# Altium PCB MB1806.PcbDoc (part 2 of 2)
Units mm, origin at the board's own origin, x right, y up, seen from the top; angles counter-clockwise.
Board outline 43.1 x 47.12 mm, 4 copper layers (Top Layer, Internal 1, Internal 2, Bottom Layer), stack 1.565 mm thick; 88 components, 68 nets, 317 pads, 562 vias.
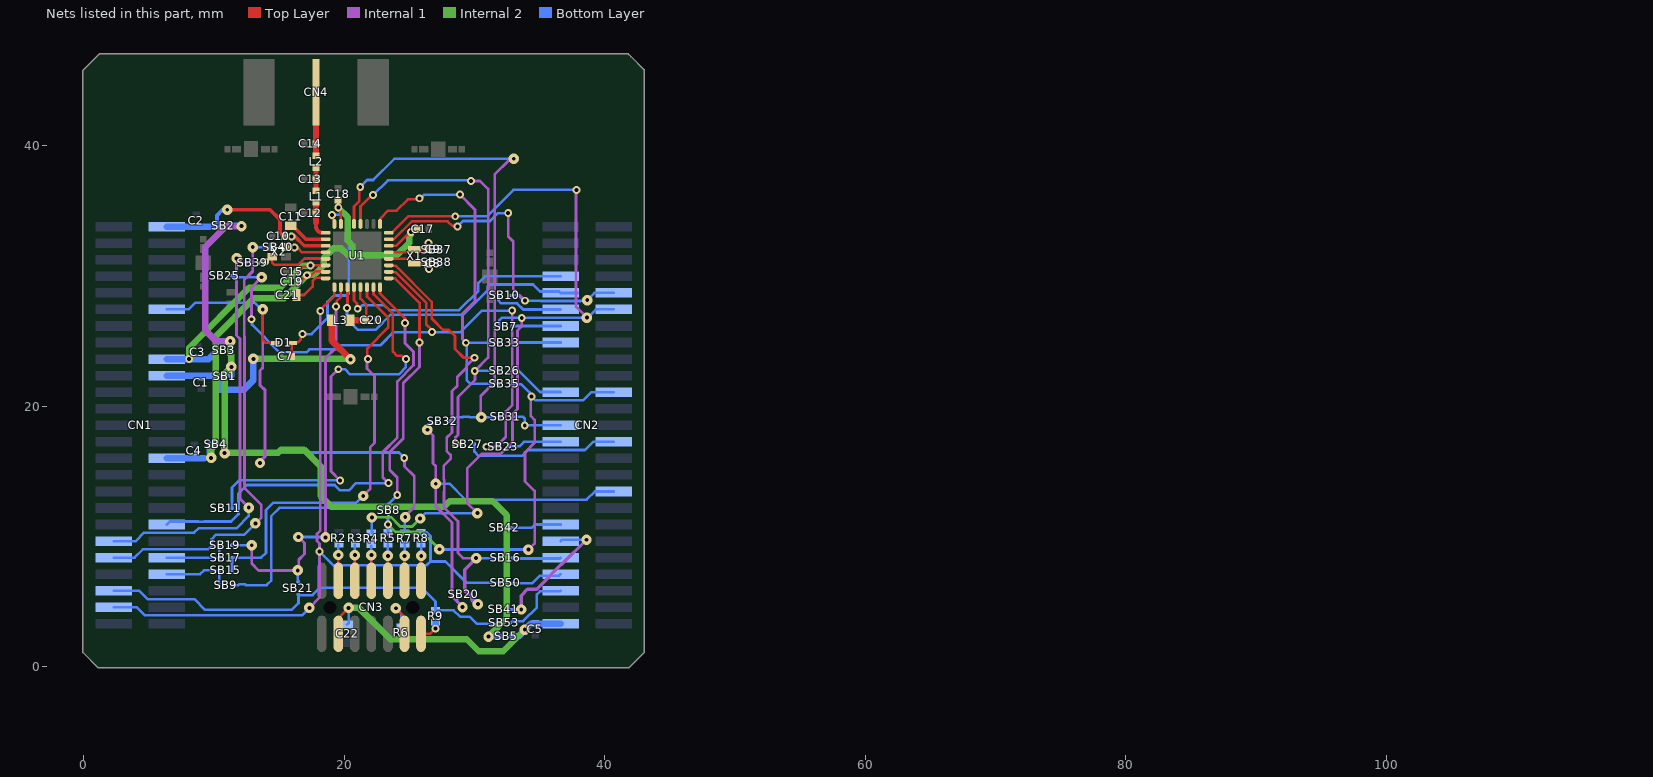
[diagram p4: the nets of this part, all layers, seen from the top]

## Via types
v1: diameter 0.6, hole 0.3, Top Layer to Bottom Layer, tented both sides, 505 vias
v2: diameter 0.8, hole 0.3, Top Layer to Bottom Layer, tented both sides, 57 vias

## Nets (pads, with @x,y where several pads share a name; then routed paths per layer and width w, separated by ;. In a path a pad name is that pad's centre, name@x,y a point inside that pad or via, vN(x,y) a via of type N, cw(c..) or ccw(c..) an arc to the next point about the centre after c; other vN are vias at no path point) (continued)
GPIO18: CN1.38 U1.8 | length 36.6
  Top Layer w0.2: U1.8@22.764,29.15 22.764,28.667 22.769,28.667 24.682,26.754 v1@24.682,26.668
  Internal 1 w0.21: v1(23.406,14.113) 22.975,14.545 22.975,16.48 24.092,17.598 24.092,21.916 25.337,23.16 25.337,24.193 24.689,24.841 v1(24.689,26.388)
  Bottom Layer w0.2: CN1.38@6.398,10.928 6.637,11.167 8.797,11.167 8.814,11.15 9.27,11.15 9.286,11.167 11.342,11.167 11.899,11.723 11.899,13.298 12.561,13.961 19.284,13.961 19.69,13.554 20.379,13.554 20.938,14.113 v1(23.406,14.113)
GPIO21: CN1.42 SB17.1 SB19.1 | length 4.9
  Bottom Layer w0.2: CN1.42@6.398,8.388 SB17.1@10.375,8.388 ; SB17.1@10.428,8.381 SB19.1@10.428,9.309
GPIO22: CN1.44 SB9.1 SB15.1 | length 5.3
  Bottom Layer w0.2: CN1.44@6.398,7.118 8.944,7.118 9.239,7.413 SB15.1@10.435,7.413 SB9.1@10.435,6.277
GPIO23: CN1.45 R9.1 SB21.1 SB53.2 | length 32.8
  Bottom Layer w0.2: CN1.45@2.334,5.848 4.274,5.848 4.925,5.198 8.522,5.198 9.337,4.382 15.987,4.382 16.506,4.901 SB21.1@16.506,5.512 ; SB21.1@16.481,5.512 SB21.1@16.506,5.512 ; SB21.1@16.506,5.603 SB21.1@16.506,5.512 ; SB53.2@31.802,3.379 31.787,3.379 31.717,3.308 30.193,3.308 29.643,3.858 28.906,3.858 28.415,4.35 R9.1@27.024,4.35 27.024,5.009 25.952,6.081 18.164,6.081 17.596,5.512 SB21.1@16.506,5.512
GPIO24: CN1.47 R8.2 SB50.1 U1.1 | length 59.1
  Top Layer w0.2: v1@18.015,27.227 19.264,28.475 U1.1@19.264,29.15
  Internal 1 w0.21: v2(17.336,4.537) 18.123,5.325 v1(18.123,8.855) 18.123,9.478 17.925,9.676 17.925,10.219 18.182,10.475 v1(18.182,27.312)
  Bottom Layer w0.2: CN1.47@2.334,4.578 4.102,4.578 4.728,3.953 16.777,3.953 17.336,4.512 v2(17.336,4.537)
  Bottom Layer w0.21: v1(18.123,8.855) 19.165,7.814 26.353,7.814 26.632,8.093 ; R8.2@25.922,10.328 26.353,10.328 26.632,10.049 26.632,8.093 ; SB50.1@31.922,6.445 31.915,6.452 29.421,6.452 27.78,8.093 26.632,8.093
GPIO28: CN2.7 U1.4 | length 19
  Top Layer w0.2: U1.4@20.764,29.15 20.764,28.134 21.001,27.897 21.001,27.542 v1(21.048,27.495)
  Bottom Layer w0.2: v1(21.048,27.495) 21.138,27.495 21.393,27.751 23.103,27.751 23.473,27.381 28.842,27.381 30.31,28.849 30.31,29.468 30.82,29.978 CN2.7@36.624,29.978
GPIO29: CN2.9 U1.3 | length 22.4
  Top Layer w0.2: v1(20.231,27.542) 20.264,27.574 U1.3@20.264,29.15
  Bottom Layer w0.2: v1(20.231,27.542) 20.231,26.723 21.076,25.879 22.416,25.879 23.568,27.031 29.165,27.031 31.026,28.893 31.026,29.236 31.144,29.353 34.509,29.353 35.045,28.818 36.515,28.818 CN2.9@36.624,28.708
  Bottom Layer w0.21: CN2.9@36.624,28.708 CN2.9@37.926,28.708
GPIO30: CN2.10 SB10.1 U1.15 | length 25.9
  Top Layer w0.2: U1.15@23.439,32.825 23.458,32.844 23.837,32.844 25.199,34.206 27.96,34.206 28.317,33.848 28.665,33.848 v1(28.715,33.798)
  Internal 1 w0.21: v1(32.601,34.835) 32.601,33.055 32.982,32.674 32.982,29.014 v1(33.886,28.11)
  Bottom Layer w0.2: v1(28.715,33.798) 29.143,34.225 31.21,34.225 31.82,34.835 v1(32.601,34.835) ; SB10.1@32.826,28.514 33.388,28.514 33.791,28.11 35.103,28.11 35.124,28.09 38.125,28.09 38.138,28.103 38.616,28.103 39.221,28.708 CN2.10@40.688,28.708
  other v2: 38.672,28.159
GPIO31: CN2.11 SB10.2 | length 5.4
  Bottom Layer w0.21: SB10.2@31.851,28.423 31.851,28.117 32.059,27.909 33.289,27.909 33.76,27.438 CN2.11@36.624,27.438
GPIO32: CN2.12 R4.2 SB7.1 U1.16 | length 63.4
  Top Layer w0.2: U1.16@23.439,33.325 23.471,33.358 23.696,33.358 24.924,34.585 v1(28.537,34.585)
  Internal 1 w0.21: v2(30.239,11.802) 29.452,12.589 29.452,15.227 30.563,16.338 32.007,16.338 32.931,17.263 32.931,19.422 33.312,19.803 33.312,25.822 33.643,26.153 v1(33.643,26.788) ; v1(37.849,36.618) 37.808,36.578 37.808,27.651 v2(38.646,26.813)
  Internal 2 w0.21: v2(22.136,11.471) 22.195,11.471 22.216,11.493 23.611,11.493 24.318,10.786 25.235,10.786 v2(25.845,11.395)
  Bottom Layer w0.2: R4.2@22.118,10.302 22.187,10.372 22.136,10.423 v2(22.136,11.471) ; v2(25.845,11.395) 26.251,11.802 v2(30.239,11.802) ; v1(28.537,34.585) 30.976,34.585 33.008,36.617 v1(37.849,36.618) v1(37.849,36.618) ; SB7.1@31.922,26.2 31.922,26.617 32.093,26.788 v1(33.643,26.788) 38.672,26.788 39.323,27.438 CN2.12@40.688,27.438
GPIO33: CN2.13 SB7.2 | length 3.7
  Bottom Layer w0.2: SB7.2@32.897,26.2 32.929,26.168 CN2.13@36.624,26.168
GPIO34: CN2.15 SB33.1 | length 3.8
  Bottom Layer w0.2: SB33.1@32.844,24.832 32.91,24.898 CN2.15@36.624,24.898
GPIO37: CN2.21 SB26.1 | length 4.5
  Bottom Layer w0.2: SB26.1@32.833,22.731 33.419,22.731 35.045,21.105 36.607,21.105 CN2.21@36.624,21.088
GPIO38: CN2.22 R5.2 SB8.1 SB35.1 | length 34.1
  Internal 1 w0.21: v2(34.151,9.008) 34.176,9.008 34.633,9.465 34.633,13.505 33.897,14.242 33.897,16.47 34.633,17.207 34.633,18.964 34.343,19.255 34.343,20.715 v1(34.389,20.762)
  Internal 2 w0.21: v1(23.381,10.938) 23.965,10.354 25.997,10.354 v2(27.318,9.033)
  Bottom Layer w0.2: R5.2@23.376,10.328 23.376,11.402 ; v2(27.318,9.033) v2@27.343,9.008 ; SB35.1@32.829,21.708 32.834,21.712 32.866,21.712 32.871,21.708 33.599,21.708 34.243,21.064 34.243,21.017 34.389,20.87 v1(34.389,20.762) 34.399,20.762 34.706,20.454 38.351,20.454 38.985,21.088 CN2.22@40.688,21.088
  Bottom Layer w0.21: v2@27.343,9.008 v2(34.151,9.008)
GPIO41: CN2.25 SB31.2 | length 4.3
  Bottom Layer w0.2: SB31.2@32.911,19.193 33.745,19.193 33.871,19.066 33.871,18.548 CN2.25@36.624,18.548
  other v1: 33.871,18.533
GPIO42: CN2.27 SB23.2 | length 3.9
  Bottom Layer w0.2: 32.913,16.932 33.465,16.932 33.811,17.278 CN2.27@36.624,17.278
GPIO43: CN2.28 SB27.1 | length 11.9
  Bottom Layer w0.2: SB27.1@29.999,17.107 29.999,16.526 30.329,16.196 33.668,16.196 34.125,16.653 38.494,16.653 39.119,17.278 CN2.28@40.688,17.278
GPIO46: CN2.34 SB20.2 SB32.2 | length 31.3
  Internal 1 w0.21: v2(26.404,18.202) 26.835,17.771 26.835,15.612 27.039,15.408 v2(27.039,14.062) 27.039,12.334 28.283,11.089 28.283,5.401 v2(29.096,4.588)
  Internal 2 w0.21: v2(29.096,4.588) v2@29.147,4.588
  Bottom Layer w0.2: v2@26.412,18.21 v2(26.404,18.202) 26.404,18.456 26.632,18.685 26.894,18.685 ; v2@27.039,14.163 v2(27.039,14.062) 28.086,14.062 29.305,12.843 38.621,12.843 39.246,13.468 CN2.34@40.688,13.468 ; SB20.2@28.7,5.579 28.7,5.005 29.096,4.609 v2(29.096,4.588)
GPIO49: CN2.37 SB42.1 | length 3.9
  Bottom Layer w0.2: SB42.1@32.813,10.674 34.389,10.674 34.643,10.928 CN2.37@36.624,10.928
GPIO50: CN2.39 SB41.1 | length 10.7
  Internal 1 w0.254: v2(33.602,4.41) 33.602,5.472 34.082,5.952 34.781,5.952 35.911,7.082 35.911,7.096 36.679,7.864 36.713,7.864 v2(38.612,9.764)
  Bottom Layer w0.2: SB41.1@32.753,4.41 v2(33.602,4.41) ; CN2.39@36.624,9.658 36.73,9.764 v2(38.612,9.764)
GPIO52: CN2.41 SB16.2 | length 3.8
  Bottom Layer w0.2: SB16.2@32.91,8.371 32.925,8.371 32.975,8.321 36.557,8.321 CN2.41@36.624,8.388
GPIO54: CN2.45 SB53.1 | length 5.5
  Bottom Layer w0.2: SB53.1@32.777,3.379 32.789,3.379 32.921,3.511 33.744,3.511 34.807,4.574 34.807,5.57 35.045,5.807 36.583,5.807 CN2.45@36.624,5.848
GPIO55: CN2.43 SB50.2 | length 4
  Bottom Layer w0.2: SB50.2@32.897,6.445 32.912,6.445 32.948,6.408 34.444,6.408 35.045,7.009 36.515,7.009 CN2.43@36.624,7.118
NetC7_2: C7.2 D1.1 U1.24 | length 15.6
  Top Layer w0.2: D1.1@16.059,24.869 16.109,24.919 16.477,24.919 16.669,25.111 v1@16.669,25.299 ; v1(19.078,34.697) 19.154,34.62 19.154,34.362 19.264,34.252 U1.24@19.264,34 U1.24@19.245,34.019
  Top Layer w0.21: C7.2@15.997,23.83 15.997,24.807 D1.1@16.059,24.869
  Bottom Layer w0.21: v1(16.805,25.543) 17.514,25.543 18.737,26.767 18.737,28.026 19.225,28.514 20.237,28.514 20.36,28.637 20.36,34.574 20.237,34.697 v1(19.078,34.697)
NetC8_2: C8.2 SB38.1 U1.12 X1.2 | length 3.2
  Top Layer w0.2: U1.12@23.439,31.325 24.826,31.325 25.021,31.13 25.021,31.08 25.078,31.022 26.153,31.022 C8.2@26.212,30.964 ; X1.2@25.093,30.93 X1.2@25.343,30.93
  other v1: 26.521,30.542
NetC9_2: C9.2 SB37.1 U1.13 X1.1 | length 3
  Top Layer w0.2: U1.13@23.439,31.825 24.888,31.825 25.093,32.03 X1.1@25.343,32.03 ; X1.1@25.306,32.068 X1.1@25.343,32.032 ; X1.1@25.421,32.03 26.291,32.03 26.369,32.108 C9.2@26.374,32.113
  other v1: 26.49,32.531
NetC11_2: C11.2 U1.26 | length 3
  Top Layer w0.3: C11.2@16.057,33.866 17.097,32.825 U1.26@18.589,32.825
NetC12_2: C12.2 L1.1 U1.25 | length 2.5
  Top Layer w0.3: 17.856,33.811 ccw(c18.342,33.811) 18.342,33.325 U1.25@18.589,33.325
  Top Layer w0.4: C12.2@17.823,34.852 C12.2@17.856,34.885
  Top Layer w0.45: 17.859,34.116 17.859,34.844 L1.1@17.859,35.54
NetC13_2: C13.2 L1.2 L2.1 | length 1.8
  Top Layer w0.4: L1.2@17.805,36.569 L1.2@17.819,36.556 ; L1.2@17.854,36.556 C13.2@17.854,37.43 L2.1@17.854,38.335
NetC14_2: C14.2 CN4.1 L2.2 | length 4.7
  Top Layer w0.45: L2.2@17.854,39.236 C14.2@17.854,40.142 CN4.1@17.854,43.891
NetC20_2: C20.2 L3.2 U1.5 | length 3.8
  Top Layer w0.2: L3.2@20.635,26.617 L3.2@20.642,26.624 ; U1.5@21.264,29.15 21.251,29.138 21.251,28.276 21.697,27.831 21.697,26.624 C20.2@21.729,26.624
  Top Layer w0.5: L3.2@20.642,26.624 C20.2@21.697,26.624
NetC21_2: C21.2 U1.32 | length 3
  Top Layer w0.2: C21.2@16.349,28.545 16.937,28.545 17.595,29.203 17.595,29.636 17.817,29.858 U1.32@18.52,29.858
NetCN3_4: CN3.4 R2.1 | length 2.8
  Top Layer w0.2: CN3.4@19.561,6.614 v2(19.561,8.589) v2@19.561,8.639
  Bottom Layer w0.2: v2(19.561,8.589) R2.1@19.561,9.384
NetCN3_6: CN3.6 R3.1 | length 2.8
  Top Layer w0.2: CN3.6@20.831,6.614 v2(20.831,8.579)
  Bottom Layer w0.2: v2(20.831,8.579) R3.1@20.831,9.372
NetCN3_8: CN3.8 R4.1 | length 2.7
  Top Layer w0.2: CN3.8@22.101,6.614 v2(22.101,8.579)
  Bottom Layer w0.2: v2(22.101,8.579) R4.1@22.101,9.31
NetCN3_10: CN3.10 R5.1 | length 2.8
  Top Layer w0.2: CN3.10@23.371,6.614 v2(23.371,8.519)
  Bottom Layer w0.2: v2(23.371,8.519) R5.1@23.371,9.423
NetCN3_11: CN3.11 R6.2 | length 3.9
  Top Layer w0.2: v2(23.976,4.504) 23.951,4.504 24.641,3.814 CN3.11@24.641,2.544
  Bottom Layer w0.2: v2(23.976,4.504) 24.386,4.094 R6.2@24.386,3.081
NetCN3_12: CN3.12 R7.1 | length 2.8
  Top Layer w0.2: CN3.12@24.641,6.614 24.641,8.519 v2(24.651,8.529)
  Bottom Layer w0.2: v2(24.651,8.529) R7.1@24.651,9.396
NetCN3_13: CN3.13 R9.2 | length 1.6
  Top Layer w0.2: CN3.13@25.911,2.544 26.591,2.544 v1@26.901,2.854
  Bottom Layer w0.5: v1@27.024,2.947 R9.2@27.024,3.45
  other v1: 27.013,2.937
NetCN3_14: CN3.14 R8.1 | length 2.8
  Top Layer w0.2: CN3.14@25.911,6.614 25.911,8.539 25.921,8.529 v2(25.926,8.529)
  Bottom Layer w0.2: v2(25.926,8.529) R8.1@25.926,9.424
NetSB1_1: SB1.1 SB2.1 SB3.1 SB4.1 SB5.1 | length 60.4
  Internal 1 w0.5: v2(11.265,25.01) 10.173,25.01 9.36,25.822 9.36,32.249 10.941,33.829 v2(12.129,33.829)
  Internal 2 w0.5: v2(11.265,25.01) 11.265,23.994 11.355,23.904 v2(11.355,23.028) 10.833,22.507 v2(10.833,16.41) 10.873,16.45 14.948,16.45 15.187,16.688 16.92,16.688 18.199,15.408 18.199,13.122 19.012,12.31 27.699,12.31 28.105,12.716 31.433,12.716 32.489,11.66 32.489,3.73 v2(31.087,2.327)
  Bottom Layer w0.5: SB4.1@10.651,17.107 10.84,16.918 10.84,16.41 v2(10.833,16.41) ; SB2.1@11.214,33.846 12.101,33.846 12.123,33.823 v2(12.129,33.829) ; v2(11.265,25.01) 11.269,25.006 SB3.1@11.269,24.295 ; SB1.1@11.355,22.342 v2(11.355,23.028) ; v2(31.087,2.327) 31.103,2.343 SB5.1@31.947,2.343
NetSB8_2: SB8.2 SB9.2 U1.9 | length 37.6
  Top Layer w0.2: U1.9@23.439,29.825 23.932,29.825 25.812,27.945 25.812,27.44 25.794,27.423
  Top Layer w0.21: v1(25.794,24.908) 25.794,27.423
  Internal 1 w0.21: v1(24.085,13.205) 24.085,14.552 23.508,15.129 23.508,16.504 24.549,17.546 24.549,21.781 25.794,23.026 v1(25.794,24.908)
  Bottom Layer w0.2: SB9.2@11.4,6.277 11.897,6.277 11.952,6.332 12.407,6.332 12.462,6.277 14.067,6.277 14.415,6.625 14.415,11.573 15.05,12.208 23.12,12.208 SB8.2@23.421,12.509 24.118,13.205 v1(24.085,13.205)
NetSB11_2: SB11.2 U1.7 | length 32.3
  Top Layer w0.2: U1.7@22.264,29.15 22.264,28.619 22.772,28.111 22.772,28.109 23.742,27.139 23.745,27.139 23.745,24.595 23.751,24.589 23.751,24.561 23.753,24.559 23.753,24.2 24.075,23.878 24.462,23.878 24.702,23.638 v1(24.753,23.638)
  Internal 1 w0.21: v1(19.561,22.851) 19.001,22.29 19.001,15.022 v1(19.705,14.317)
  Bottom Layer w0.2: SB11.2@11.399,12.177 11.399,13.764 11.976,14.342 19.681,14.342 v1(19.705,14.317) ; v1@19.52,22.851 v1(19.561,22.851) 20.076,22.851 20.473,22.454 24.203,22.454 24.753,23.003 v1(24.753,23.638)
NetSB15_2: SB15.2 SB17.2 U1.6 | length 32.7
  Top Layer w0.2: U1.6@21.764,29.15 21.764,28.42 23.381,26.803 23.381,26.051 21.789,24.459 v1@21.789,23.741
  Internal 1 w0.21: v2(21.476,13.122) 22.009,13.656 22.009,16.856 22.34,17.186 22.34,22.317 21.764,22.893 v1@21.764,23.556
  Bottom Layer w0.2: SB15.2@11.403,7.42 SB17.2@11.403,8.381 13.635,8.381 14.008,8.754 14.008,12.03 14.567,12.589 20.938,12.589 v2@21.474,13.125
  other v1: 21.84,23.635
NetSB16_1: SB16.1 SB20.1 U1.11 | length 36.3
  Top Layer w0.2: U1.11@23.439,30.825 23.458,30.806 23.952,30.806 26.734,28.024 26.734,27.189
  Top Layer w0.21: 26.734,27.189 26.734,26.737 27.595,25.875 28.038,25.875 28.516,25.397 28.516,24.409 29.192,23.734 v1(30.024,23.734)
  Internal 1 w0.21: v1(30.024,23.734) 29.41,23.12 29.41,22.962 28.69,22.241 28.69,21.573 28.291,21.174 28.291,18.007 27.877,17.593 27.877,16.584 28.183,16.278 28.183,15.971 27.66,15.448 27.66,14.367 27.694,14.333 27.694,13.454 27.682,13.442 27.682,12.234 28.741,11.175 28.741,8.743 29.136,8.347 v2(30.137,8.347)
  Internal 1 w0.254: v2(30.137,8.347) 29.267,7.477 29.267,5.835 v2(30.277,4.825)
  Bottom Layer w0.2: SB20.1@29.675,5.579 29.675,5.564 29.794,5.445 29.794,5.081 29.936,4.94 30.162,4.94 v2(30.277,4.825) ; v2(30.137,8.347) 31.873,8.347 31.887,8.361 31.925,8.361 SB16.1@31.935,8.371
NetSB19_2: SB19.2 SB21.2 U1.2 | length 32.4
  Top Layer w0.2: v1(19.381,27.671) 19.431,27.721 19.431,28.069 19.764,28.402 U1.2@19.764,29.15
  Internal 1 w0.21: v2(12.916,9.338) 12.916,7.941 13.45,7.407 v2(16.452,7.407) 16.523,7.407 16.523,8.225 16.959,8.661 16.959,9.511 v2(16.498,9.973) ; v2(18.58,9.947) 18.58,23.714 19.327,24.461
  Internal 1 w0.254: 19.327,24.461 19.381,24.515 v1(19.381,27.671)
  Bottom Layer w0.2: SB19.2@11.375,9.337 11.402,9.363 11.427,9.338 v2(12.916,9.338) ; v2(16.452,7.407) 16.452,6.632 SB21.2@16.506,6.578
  Bottom Layer w0.21: v2(16.498,9.973) 18.555,9.973 v2(18.58,9.947)
NetSB23_1: SB23.1 SB25.1 U1.10 | length 47.6
  Top Layer w0.2: U1.10@23.439,30.325 23.458,30.306 23.957,30.306 26.302,27.961 26.302,27.651
  Top Layer w0.21: 26.302,27.651 26.302,26.305 26.785,25.822 26.785,25.695 v1(26.759,25.695)
  Internal 1 w0.21: v1(12.893,26.686) 12.893,29.126 v2(13.678,29.912) ; v1(30.94,16.9) 30.947,16.893 31.648,16.893 32.423,17.669 32.423,19.599 32.906,20.082 v1(32.906,27.346)
  Bottom Layer w0.2: v1(30.94,16.9) 30.941,16.901 31.955,16.901
  Bottom Layer w0.21: SB25.1@11.352,30.022 11.462,29.912 v2(13.678,29.912) ; v1(12.893,26.686) 12.93,26.648 12.93,26.273 15.058,24.146 17.108,24.146 17.337,24.375 19.486,24.375 19.805,24.693 22.81,24.693 23.813,25.695 v1(26.759,25.695) 28.941,25.695 30.592,27.346 v1(32.906,27.346)
NetSB26_2: SB26.2 SB27.2 U1.20 | length 34.9
  Top Layer w0.2: U1.20@21.264,34 21.264,35.348 21.414,35.498 22.131,36.215 v1(22.235,36.215)
  Internal 1 w0.21: v1(28.585,17.11) 28.539,17.155 28.539,17.602 28.749,17.812 28.749,20.706 30.061,22.018 v1@30.061,22.495 ; v1(29.75,37.301) 29.753,37.303 30.442,37.303 31.066,36.68 31.066,23.753 v1(30.036,22.724)
  Bottom Layer w0.2: v1(22.235,36.215) 23.374,37.354 29.697,37.354 v1(29.75,37.301) ; v1(28.585,17.11) 28.586,17.109 29.023,17.109 SB27.2@29.024,17.107 ; v1@30.087,22.731 SB26.2@31.858,22.731
NetSB31_1: SB31.1 SB32.1 U1.21 | length 41.4
  Top Layer w0.2: U1.21@20.764,34 20.764,35.343 21.18,35.759 21.18,36.779 v1(21.247,36.846)
  Internal 1 w0.21: v2(30.544,19.168) 30.544,18.939 30.493,18.888 30.493,19.168 30.493,20.793 31.56,21.86 31.56,37.786 32.666,38.892 32.912,38.892 v2(33.025,39.005)
  Bottom Layer w0.2: v1(21.247,36.846) 21.772,37.371 22.229,37.371 23.864,39.005 v2(33.025,39.005) ; SB32.1@28.069,18.845 28.392,19.168 29.107,19.168 29.149,19.21 29.605,19.21 29.647,19.168 v2(30.544,19.168) SB31.1@31.939,19.168
NetSB33_2: SB33.2 SB35.2 U1.17 | length 27.6
  Top Layer w0.2: U1.17@22.764,34 22.783,34.019 22.783,34.41 23.394,35.021 24.029,35.021 24.898,35.89 25.729,35.89 v1(25.805,35.966)
  Internal 1 w0.21: v1(28.893,36.262) 30.061,35.093 30.061,28.083 30.015,28.037 ; v1(29.35,24.883) 29.096,25.137 29.096,27.117 30.015,28.035
  Bottom Layer w0.2: v1(25.805,35.966) 25.853,35.966 26.123,36.236 v1@28.918,36.236 ; SB35.2@31.842,21.723 29.699,21.723 29.41,22.012 29.41,24.833 29.35,24.893 SB33.2@31.852,24.893
NetSB39_1: SB39.1 U1.29 X2.1 | length 4.8
  Top Layer w0.2: X2.1@14.501,31.48 14.501,31.02 14.642,30.878 16.497,30.878 16.966,31.347 17.206,31.347 17.21,31.351 17.665,31.351 17.669,31.347 18.271,31.347 18.274,31.344 18.57,31.344 U1.29@18.589,31.325
  other v1: 13.958,31.099
NetSB40_1: SB40.1 U1.28 X2.3 | length 3.3
  Top Layer w0.2: v1(16.193,32.198) 16.269,32.121 16.498,32.121 16.794,31.825 U1.28@18.589,31.825
  Bottom Layer w0.2: SB40.1@15.424,32.198 v1(16.193,32.198)
NRST: CN1.12 D1.2 R7.2 | length 42.2
  Top Layer w0.2: v2(13.764,27.438) 13.764,25.088 13.983,24.869 D1.2@14.709,24.869
  Internal 1 w0.21: v2@13.438,15.763 v2(13.551,15.65) ; 13.551,21.617 13.551,22.749 13.764,22.962 v2(13.764,27.438) ; v1(24.626,16.043) 24.626,15.769 24.651,15.743 24.651,15.383 25.392,14.642 25.392,12.263 24.702,11.573 v2(24.702,11.493)
  Internal 1 w0.254: v2(13.551,15.65) 13.551,15.769 13.937,16.154 13.937,21.232 13.551,21.617
  Bottom Layer w0.2: CN1.12@6.398,27.438 8.061,27.438 8.587,27.964 13.137,27.964 13.932,27.169 13.983,27.219 v2(13.764,27.438) ; R7.2@24.658,10.303 v2@24.658,11.479
  Bottom Layer w0.21: v2(13.551,15.65) 13.551,15.783 14.218,16.45 24.219,16.45 v1(24.626,16.043)
OSC_IN: CN1.39 SB39.2 | length 32.2
  Internal 1 w0.21: v2(11.753,31.36) 11.753,25.448 12.01,25.191 12.01,12.911 v2(12.688,12.233)
  Bottom Layer w0.2: CN1.39@2.334,9.658 4.017,9.658 4.661,10.302 8.496,10.302 8.852,10.659 11.773,10.659 12.688,11.573 v2(12.688,12.233) ; v2(11.753,31.36) 11.773,31.379 12.123,31.029 SB39.2@12.518,31.029
OSC_OUT: CN1.41 SB40.2 | length 35.9
  Internal 1 w0.21: v2(12.992,32.223) 12.992,30.369 12.338,29.714 12.338,25.372 12.37,25.34 12.37,13.719 13.653,12.437 13.653,11.471 v2(13.196,11.014)
  Bottom Layer w0.2: CN1.41@2.334,8.388 3.915,8.388 4.56,9.033 9.557,9.033 9.825,9.301 9.825,9.79 10.186,10.151 12.357,10.151 13.221,11.014 v2(13.196,11.014) ; v2@13.069,32.198 SB40.2@14.449,32.198
VDD1: C2.2 C10.1 CN1.2 SB2.2 U1.27 | length 14.9
  Top Layer w0.3: v2@11.011,35.093 v2(11.037,35.093) 14.313,35.093 15.077,34.33 15.077,33.369 C10.1@15.401,33.045 15.419,33.026 v1(15.971,33.026) 16.244,33.026 16.945,32.325 U1.27@18.589,32.325
  Bottom Layer w0.3: SB2.2@10.239,33.846 10.239,34.651 10.681,35.093 v2(11.037,35.093)
  Bottom Layer w0.5: CN1.2@6.398,33.788 10.181,33.788 SB2.2@10.239,33.846
VDD3: C3.2 C15.1 CN1.18 SB3.2 U1.30 | length 19.3
  Top Layer w0.2: C15.1@16.446,30.342 16.446,30.367 16.601,30.522 16.651,30.522 16.853,30.724 17.361,30.724 17.462,30.825 U1.30@18.589,30.825
  Internal 2 w0.5: v1(8.116,23.638) 8.116,24.502 12.713,29.099 15.101,29.099 16.802,30.801 v1(17.437,30.801)
  Bottom Layer w0.5: CN1.18@6.398,23.628 9.627,23.628 SB3.2@10.294,24.295
VDD4: C4.2 C17.1 C18.1 C19.1 CN1.30 SB4.2 U1.14 U1.23 U1.31 | length 42.7
  Top Layer w0.2: C19.1@16.453,29.556 16.625,29.556 v1@17.107,30.039 ; 17.463,30.039 17.782,30.358 U1.31@18.52,30.358 ; v1@19.546,35.287 C18.1@19.546,35.837 ; v1(19.561,35.271) 19.561,35.163 19.764,34.961 U1.23@19.764,34 ; U1.14@23.439,32.325 24.009,32.326 25.06,33.376 v1(25.147,33.376)
  Internal 2 w0.5: v2(9.795,16.046) 9.795,16.735 10.173,17.113 10.173,25.391 13.094,28.312 15.405,28.312 v1(17.158,30.064) 17.177,30.083 17.71,30.083 18.45,30.823 18.45,31.383 19.19,32.123 19.77,32.123 20.28,31.614 20.638,31.614 ; v1(19.561,35.271) 19.561,35.244 20.28,34.525 20.28,32.728 20.638,32.37 20.638,31.614 ; v1(25.147,33.376) 25.128,33.357 25.128,33.19 25.022,33.084 25.022,32.565 24.07,31.614 20.638,31.614
  Bottom Layer w0.5: CN1.30@6.398,16.008 9.274,16.008 ; v2@9.676,16.41 SB4.2@9.676,17.107
VDD15: C5.2 C22.2 CN2.49 CN3.3 SB5.2 | length 23.4
  Top Layer w0.2: CN3.3@19.561,2.544 19.561,3.764 20.326,4.529 v2(20.351,4.529)
  Internal 2 w0.5: v2(20.351,4.529) 21.154,4.529 23.559,2.124 29.426,2.124 30.341,1.21 32.22,1.21 v2(33.871,2.861)
  Bottom Layer w0.2: C22.2@20.231,3.254 20.351,3.375 v2(20.351,4.529)
  Bottom Layer w0.5: SB5.2@32.922,2.343 33.404,2.343 33.871,2.81 v2(33.871,2.861) 34.319,3.308 34.474,3.308 34.492,3.326 C5.2@34.678,3.326 ; C5.2@34.678,3.308 CN2.49@36.624,3.308
VDDA: C1.2 CN1.20 L3.1 SB1.2 | length 20.7
  Top Layer w0.5: L3.1@19.049,26.612 19.049,25.056 v2(20.496,23.609)
  Internal 2 w0.5: v2(13.043,23.638) 20.46,23.638 20.485,23.663 v2@20.46,23.663
  Bottom Layer w0.5: CN1.20@6.398,22.358 10.339,22.358 SB1.2@10.368,22.329 10.368,21.259 12.28,21.259 13.043,22.022 v2(13.043,23.638)
pads on no net: CN1.3 CN1.4 CN1.5 CN1.10 CN1.11 CN1.16 CN1.19 CN1.21 CN1.23 CN1.24 CN1.26 CN1.27 CN1.29 CN1.32 CN1.43 CN1.48 CN1.50 CN2.1 CN2.3 CN2.4 CN2.5 CN2.6 CN2.16 CN2.17 CN2.18 CN2.19 CN2.23 CN2.24 CN2.29 CN2.30 CN2.31 CN2.33 CN2.35 CN2.36 CN2.40 CN2.42 CN2.46 CN2.47 CN2.48 CN3.1 CN3.2 CN3.9 CN3.NPTH1 CN3.NPTH2 Designator15.1

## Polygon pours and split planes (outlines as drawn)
GND on Top Layer "Top Layer-GND" (solid, remove dead copper, pour order 9): -6.693,52.045 44.006,52.045 44.006,-1.076 -6.693,-1.076
NetC12_2 on Top Layer "RF_OUT" (solid, pour order 5): 18.086,34.103 18.004,33.83 17.707,33.82 17.641,34.077
GND on Bottom Layer "Bottom Layer-GND" (solid, remove dead copper, pour order 7): -3.848,46.634 43.676,46.634 43.676,-1.508 -3.848,-1.508
GND on Internal 2 "Internal 2-GND" (solid, remove dead copper, pour order 11): -4.508,46.634 47.486,46.634 47.486,-0.721 -4.508,-0.721
GND on Internal 1 "Internal 1-GND" (solid, remove dead copper, pour order 13): -2.679,46.844 15.659,46.844 15.659,31.944 19.876,31.944 19.876,46.844 44.793,46.844 44.793,-1.635 -2.679,-1.635

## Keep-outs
Top Layer:
  rectangle: 17.641,36.045 18.086,36.158
Keep-Out Layer:
  lines w0.1: 43,1.141 43,45.795 41.78,47.015 1.26,47.015 0,45.755 0,1.139 1.139,0 41.852,0 42.504,0.647 43.001,1.141

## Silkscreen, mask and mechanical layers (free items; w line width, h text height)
Top Overlay:
  lines w0.05: -0.592,0 1.139,0 ; 0,-0.5 0,1.139
  lines w0.1: 18.204,35.128 18.795,37.008 ; 9.182,20.742 31.182,20.742 31.182,39.742 9.182,39.742 9.182,20.742
  text "L" at 1.245,41.838 h7.62
  text "MB1806A" at 2.769,1.988 h2.5
Bottom Overlay:
  text "H" at 40.962,42.376 h7.62
  text "C" at 35.288,41.106 h7.62
  text "I" at 40.505,38.176 h7.62
Top Solder:
  lines w1: 9.182,28.058 9.182,20.742 17.615,20.742 ; 9.182,33.925 9.182,39.742 9.944,39.742 ; 19.816,39.732 24.219,39.767 ; 23.371,20.742 31.153,20.742 31.153,26.813 ; 30.137,39.792 31.153,39.792 31.153,33.026
M1-Board Shape:
  lines w0.1: 43,1.141 43,45.795 ; 43.001,1.141 41.852,0 1.139,0 0,1.139 0,45.75 0,45.755 1.245,47 41.326,47.015 41.78,47.015 41.987,46.809 43,45.795 ; 43.001,45.795 43,45.795
M2-Board Dimensions:
  lines w0.1: -5.613,47 0.61,47 ; -5.334,0 0.889,0 ; 0,-11.198 0,0.464 ; 43,-10.994 43,0.667
  lines w0.254: -5.798,2 -5.131,0 ; -5.797,45 -5.131,47 ; -5.385,0 -4.877,0 ; -5.385,47 -4.877,47 ; -5.131,19.955 -5.131,0 ; -5.131,27.045 -5.131,47 ; -4.464,2 -5.131,0 ; -4.464,45 -5.131,47 ; 0,-11.121 0,-10.613 ; 2,-11.534 0,-10.867 ; 2,-10.201 0,-10.867 ; 17.955,-10.867 0,-10.867 ; 25.045,-10.867 43,-10.867 ; 41,-11.534 43,-10.867 ; 41,-10.201 43,-10.867 ; 43,-11.121 43,-10.613
  text "47 (mm)" at -4.29,20.209 h2 r90
  text "43 (mm)" at 18.209,-11.708 h2
M4-Bottom Dimensions:
  lines w0.1: -1.323,33.788 2.334,33.788 ; 2.334,-5 2.334,33.788 ; 36.624,-5 36.624,33.788 ; 44.448,33.788 2.334,33.788
  lines w0.254: 2.334,-5.254 2.334,-4.746 ; 4.334,-5.667 2.334,-5 ; 4.334,-4.333 2.334,-5 ; 14.717,-5 2.334,-5 ; 24.242,-5 36.624,-5 ; 34.624,-5.667 36.624,-5 ; 34.624,-4.333 36.624,-5 ; 36.624,-5.254 36.624,-4.746
  text "34.29 (mm)" at 14.971,-5.841 h2
  text "CN1/CN2 spacing" at 12.954,-7.595 h2
Drill Drawing:
  drawing of 315 lines, arcs and shapes, not listed
  text "Layer" at -0.699,115.405 h1.52
  text "Name" at 9.713,115.405 h1.52
  text "Material" at 33.329,115.405 h1.52
  text "Thickness" at 55.167,115.405 h1.52
  text "Constant" at 71.673,115.405 h1.52
  text "Board Layer Stack" at 86.147,115.405 h1.52
  text "Top Overlay" at 9.713,112.357 h1.52
  text "Top Solder" at 9.713,109.309 h1.52
  text "Solder Resist" at 33.329,109.309 h1.52
  text "0,70mil" at 55.167,109.309 h1.52
  text "4.2" at 71.673,109.309 h1.52
  text "1" at -0.699,106.261 h1.52
  text "Top Layer" at 9.713,106.261 h1.52
  text "1,60mil" at 55.167,106.261 h1.52
  text "Dielectric 1" at 9.713,103.213 h1.52
  text "FR-4" at 33.329,103.213 h1.52
  text "3,00mil" at 55.167,103.213 h1.52
  text "3.7" at 71.673,103.213 h1.52
  text "2" at -0.699,100.165 h1.52
  text "Internal 1" at 9.713,100.165 h1.52
  text "1,20mil" at 55.167,100.165 h1.52
  text "Dielectric 3" at 9.713,97.117 h1.52
  text "50,00mil" at 55.167,97.117 h1.52
  text "4.5" at 71.673,97.117 h1.52
  text "3" at -0.699,94.069 h1.52
  text "Internal 2" at 9.713,94.069 h1.52
  text "1,20mil" at 55.167,94.069 h1.52
  text "Dielectric 2" at 9.713,91.021 h1.52
  text "3,00mil" at 55.167,91.021 h1.52
  text "3.7" at 71.673,91.021 h1.52
  text "4" at -0.699,87.973 h1.52
  text "Bottom Layer" at 9.713,87.973 h1.52
  text "1,60mil" at 55.167,87.973 h1.52
  text "Bottom Solder" at 9.713,84.925 h1.52
  text "Solder Resist" at 33.329,84.925 h1.52
  text "0,70mil" at 55.167,84.925 h1.52
  text "4.2" at 71.673,84.925 h1.52
  text "Bottom Overlay" at 9.713,81.877 h1.52
  text "Symbol" at -0.519,73.911 h2.16
  text "Count" at 7.943,73.911 h2.16
  text "Hole Size" at 16.721,73.911 h2.16
  text "Plated" at 32.27,73.911 h2.16
  text "Hole Type" at 39.698,73.911 h2.16
  text "Drill Layer Pair" at 50.513,73.911 h2.16
  text "Via/Pad" at 71.012,73.911 h2.16
  text "Pad Shape" at 79.873,73.911 h2.16
  text "Template" at 91.449,73.911 h2.16
  text "Description" at 105.871,73.911 h2.16
  text "562" at 7.943,70.183 h1.8
  text "11,81mil (0,30mm)" at 16.721,70.183 h1.8
  text "PTH" at 32.27,70.183 h1.8
  text "Round" at 39.698,70.183 h1.8
  text "Top Layer - Bottom Layer" at 50.513,70.183 h1.8
  text "Via" at 71.012,70.183 h1.8
  text "Rounded" at 79.873,70.183 h1.8
  text "(Mixed)" at 91.449,70.183 h1.8
  text "2" at 7.943,66.454 h1.8
  text "39,37mil (1,00mm)" at 16.721,66.454 h1.8
  text "NPTH" at 32.27,66.454 h1.8
  text "Round" at 39.698,66.454 h1.8
  text "Top Layer - Bottom Layer" at 50.513,66.454 h1.8
  text "Pad" at 71.012,66.454 h1.8
  text "Rounded" at 79.873,66.454 h1.8
  text "c0hn100m105p-1" at 91.449,66.454 h1.8
  text "564 Total" at 7.943,62.726 h1.8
